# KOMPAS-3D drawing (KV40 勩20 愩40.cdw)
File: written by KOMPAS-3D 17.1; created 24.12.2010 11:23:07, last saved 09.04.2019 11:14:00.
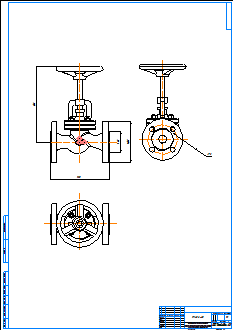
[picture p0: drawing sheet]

Title block, sheet 1: name: KV 40 Ду20; material: Внимание! Данный продукт является объектом авторского права ООО «Торговый Дом АДЛ». / Запрещается изменение, копирование, распространение / (в том числе путем копирования на другие сайты и ресурсы в Интернете) / или любое иное использование информации и объектов без предварительного / согласия правообладателя (ООО «Торговый Дом АДЛ»); scale: 1:1; sheets: 1; organisation: ООО "Торговый дом АДЛ"; sheet format: A1; stored path: \\adlc.lan\data\АДЛ_ПКД\3D-модели\ADL production\Вентили ГРАНВЕНТ\KV40\KOMPAS 2D\KV 40 Ду20.cdw

Views: Спереди 1, Проекционный вид 2, Спереди 5, Проекционный вид 6, Проекционный вид 7
Dimensions and other numbers on the sheet: 58; 105; 150; 75; 190; 1:1; 1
